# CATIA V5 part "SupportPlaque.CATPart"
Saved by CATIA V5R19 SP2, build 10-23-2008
Part number: SupportPlaque
Bounding box of the stored display mesh (mm): x 0 to 24, y -40 to 70, z -40 to 60
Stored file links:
  D:\SCHOOL\FRANCE\BANC_POUTRE_EN_MOUSSE\SupportPlaque.CATPart
  C:\Program Files\Dassault Systemes\B19\intel_a\reffiles\standard\MetricThickPitch.txt
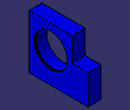
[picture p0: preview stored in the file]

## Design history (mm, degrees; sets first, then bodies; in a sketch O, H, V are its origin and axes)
AxisSystem1: origin (0, 0, 0), X (1, 0, 0), Y (0, 1, 0), Z (0, 0, 1)
Set1
  Plane1: type Offset, RefPlane face of Pad2, Offset 19.7
Body1 (main body)
  Sketch1 on yz-plane, origin (0, 0, 0), H (0, 1, 0), V (0, 0, 1)
    line L1 (40, 60) -> (40, -40)
    line L2 (40, -40) -> (-40, -40)
    line L3 (-40, -40) -> (-40, 60)
    line L4 (-40, 60) -> (40, 60)
    length L4 = 80
    distance L4 H = 60
    distance H L2 = 40
    vertical: L1 V, L3 V
    horizontal: L2 H, L4 H
    equidistance: L1 L3 O
  Pad1: profile Sketch1, direction (1, 0, 0), length 24
  Sketch2 on face of Pad1 from Sketch1.L2, origin (8.545, 11.5168, -40), H (1, 0, 0), V (0, -1, 0)
    point P1 (3.455, -8.4832)
    reference intersected line E1 through (0, 11.5168) direction (1, 0) from ZX plane of AxisSystem1
    reference intersected line E2 through (-8.545, 0) direction (0, 1) from YZ plane of AxisSystem1
    distance E1 P1 = 20
    distance E2 P1 = 12
  Hole1: placed by Sketch2, at (12, 20, -40) direction (0, 0, 1), diameter 4.917, depth 10, threaded "M6", thread diameter 6, thread depth 6, pitch 1
  RectPattern1: of Hole1, direction 1 instances 2, spacing 40, along edge [start face of Pad1 | face of Pad1 from Sketch1.L2] reversed
  Sketch3 on face of Pad1 from Sketch1.L2, origin (12.0128, 0.3947, -40), H (1, 0, 0), V (0, -1, 0)
    point P1 (-0.0128, 0.3947)
    reference intersected line E1 through (0, 0.3947) direction (1, 0) from ZX plane of AxisSystem1
    reference intersected line E2 through (-12.0128, 0) direction (0, 1) from YZ plane of AxisSystem1
    distance E2 P1 = 12
    coincidence: E1 P1
  Hole2: placed by Sketch3, at (12, 0, -40) direction (0, 0, 1), diameter 4.917, depth 5, threaded "M6", thread diameter 6, thread depth 5, pitch 1
  Sketch4 on end face of Pad1, origin (24, 0, 0), H (0, 1, 0), V (0, 0, 1)
    circle A1 centre (0, 16) radius 31
    radius A1 = 31
  Pocket1: profile Sketch4, direction (-1, 0, 0), through (limit type 6)
  Sketch5 on face of Pad1 from Sketch1.L1, origin (0, 40, 0), H (-1, 0, 0), V (0, 0, 1)
    projected line E1 (-24, 16) -> (0, 16) from Sketch7.L1
    projected line E2 (-24, -40) -> (-24, 16) from Sketch7.E2
    projected line E3 (0, 16) -> (0, -40) from Sketch7.E4
    projected line E4 (0, -40) -> (-24, -40) from Sketch7.E5
  Pad2: profile Sketch5, direction (0, 1, 0), length 30
  Sketch6 on Plane1, origin (19.7, 0, 0), H (0, 1, 0), V (0, 0, 1)
    circle A1 centre (0, 16) radius 32.5
    point P1 (0, 16)
    reference projected circle E1 centre (0, 16) radius 31 from edge [end face of Pad1 | face of Pocket1 from Sketch4.A1]
    radius A1 = 32.5
    coincidence: P1 V
    concentricity: P1 E1
  Pocket2: profile Sketch6, direction (1, 0, 0), length 2.3
  Sketch7 on face of Pad1 from Sketch1.L3, origin (0, -40, 0), H (1, 0, 0), V (0, 0, 1)
    line L1 (0, 16) -> (24, 16)
    projected line E1 (24, 60) -> (24, -40) from edge [face of Pad1 from Sketch1.L3 | end face of Pad1]
    projected line E2 (24, 16) -> (24, -40) from edge [face of Pad1 from Sketch1.L3 | end face of Pad1]
    point P2 (24, -40)
    projected line E3 (0, 60) -> (0, -40) from edge [start face of Pad1 | face of Pad1 from Sketch1.L3]
    projected line E4 (0, 16) -> (0, -40) from edge [start face of Pad1 | face of Pad1 from Sketch1.L3]
    point P4 (0, -40)
    projected line E5 (0, -40) -> (24, -40) from edge [face of Pad1 from Sketch1.L2 | face of Pad1 from Sketch1.L3]
    point P5 (0, -40)
    point P6 (24, -40)
    point P7 (24, 16)
    point P8 (0, 16)
    distance E5 L1 = 56
    horizontal: L1 H
    coincidence: E1 P7, E3 P8, P2 P6, P4 P5
  Sketch8 on start face of Pad1, origin (0, 0, 0), H (0, -1, 0), V (0, 0, 1)
    circle A1 centre (0, 16) radius 23
    point P1 (0, 16)
    reference intersected line E1 through (0, 0) direction (-1, 0) from XY plane of AxisSystem1
    distance P1 E1 = 16
    radius A1 = 23
    coincidence: P1 V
